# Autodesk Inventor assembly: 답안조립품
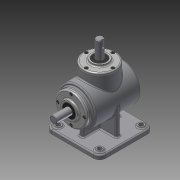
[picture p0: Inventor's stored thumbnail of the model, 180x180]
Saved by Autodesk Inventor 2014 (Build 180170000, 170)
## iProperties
Created: 2015-07
Part Number: 답안조립품
Document SubType Name: Assembly
Designer: basic
Author: basic
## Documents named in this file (14)
- C:\Users\basic\Desktop\450705V1019\답안조립품.iam
- C:\Users\basic\Desktop\450705V1019\본체.ipt
- C:\Users\basic\Desktop\450705V1019\450705V1019\서브 축.ipt
- 서브 축.ipt
- C:\Users\basic\Desktop\450705V1019\450705V1019\키 4x4.ipt
- C:\Users\basic\Desktop\450705V1019\450705V1019\서브 베벨기어.ipt
- C:\Users\basic\Desktop\450705V1019\450705V1019\베어링 6203.ipt
- C:\Users\basic\Desktop\450705V1019\450705V1019\커버.ipt
- C:\Users\basic\Desktop\450705V1019\450705V1019\오일실.ipt
- C:\Users\basic\Desktop\450705V1019\450705V1019\메인 축.ipt
- 메인 축.ipt
- C:\Users\basic\Desktop\450705V1019\450705V1019\키 5x5.ipt
- C:\Users\basic\Desktop\450705V1019\450705V1019\메인 베벨기어.ipt
- C:\Users\basic\Desktop\450705V1019\450705V1019\M4.ipt
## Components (8 placed, 1 different names)
1. M4:1
2. M4:2
3. M4:3
4. M4:4
5. M4:5
6. M4:6
7. M4:7
8. M4:8
